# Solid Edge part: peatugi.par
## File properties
Author: Romil
Template: iso part.par
Last saved by: Romil
Revision: 39
Application: Solid Edge
Material: ABS Plastic, medium impact
Face Style: Black
Fill Style: ANSI34(Plastic)
Virtual Style: Black (Shiny)
Coef. of Thermal Exp: 5.8e-05
Thermal Conductivity: 2.0
Specific Heat: 0.0
Modulus of Elasticity: 2275269810.0
Poisson's Ratio: 0.4
Yield Stress: 43436969.1
Ultimate Stress: 0.0
Elongation: 0.0
Density: 1024.000 kg/m^3
Accuracy: 0.990
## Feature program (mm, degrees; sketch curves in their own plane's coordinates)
sketch for "unnamed Protrusion 1" plane through (0, 0, 0) normal (1, 0, 0) x-axis (0, 1, 0)
  arc centre (0, 0) radius 2.35 from (2.181, 0.875) to (2.181, -0.875) cw
  arc centre (0, 0) radius 2.35 from (-0.875, 2.181) to (0.875, 2.181) cw
  arc centre (0, 0) radius 2.35 from (-2.181, -0.875) to (-2.181, 0.875) cw
extrude "unnamed Protrusion 1" add finite 7 along -normal
fillet "Round_8" radius 0.2  Radii2 = 0.2 mm
sketch for "ExtrudedCutout_2" plane through (-7, 0, 0) normal (-1, 0, 0) x-axis (0, 0, 1)
extrude "ExtrudedCutout_2" cut finite 0.1 along -normal
sketch for "unnamed Protrusion 2" plane through (0, 0, 0) normal (0, 0, 1) x-axis (1, 0, 0)
  line (0, -9.7299) -> (6.7203, -2.6937)
  line (0, 9.7299) -> (6.7203, 2.6937)
  line (-10.9663, 11.8304) -> (0, 9.7299)
  line (-11.7, 4.1) -> (0, 4.1)
  line (0, 4.1) -> (0, -4.1)
  line (-11.7, -4.1) -> (0, -4.1)
  line (-10.9663, -11.8304) -> (0, -9.7299)
extrude "unnamed Protrusion 2" add along +normal
sketch for "ExtrudedCutout_5" #1 plane through (0, 0, 0) normal (0, 0, 1) x-axis (1, 0, 0)
  circle centre (-11.7, -8) radius 2.4
sketch for "ExtrudedCutout_5" #2 plane through (0, 0, 0) normal (0, 0, 1) x-axis (1, 0, 0)
  circle centre (-11.7, 8) radius 2.4
sketch for "ExtrudedCutout_5" #3 plane through (0, 0, 0) normal (0, 0, 1) x-axis (1, 0, 0)
  circle centre (3.9, 0) radius 2.4
extrude "ExtrudedCutout_5" cut finite 96.2473 symmetric
sketch for "unnamed Cutout 1" #1 plane through (-3.9, 0, 3.9) normal (0, 0, 1) x-axis (1, 0, 0)
  circle centre (-7.8, 8) radius 3.1
sketch for "unnamed Cutout 1" #2 plane through (-3.9, 0, 3.9) normal (0, 0, 1) x-axis (1, 0, 0)
  arc centre (-7.8, 8) radius 3.9 from (-5.0431, 5.2415) to (-4.5705, 10.1864) ccw
  arc centre (-4.4049, 10.2985) radius 0.2 from (-4.5705, 10.1864) to (-4.3673, 10.495) cw
  line (-4.3673, 10.495) -> (-2.6498, 10.166)
  arc centre (-2.6875, 9.9696) radius 0.2 from (-2.4875, 9.9696) to (-2.6498, 10.166) ccw
  line (-2.4875, 5.1) -> (-2.4875, 9.9696)
  arc centre (-2.6875, 5.1) radius 0.2 from (-2.4875, 5.1) to (-2.6875, 4.9) cw
  line (-4.9017, 4.9) -> (-2.6875, 4.9)
  arc centre (-4.9017, 5.1) radius 0.2 from (-4.9017, 4.9) to (-5.0431, 5.2415) cw
sketch for "unnamed Cutout 1" #3 plane through (-3.9, 0, 3.9) normal (0, 0, 1) x-axis (1, 0, 0)
  line (-1.7648, 5.1) -> (-1.7648, 9.7545)
  arc centre (-1.5648, 9.7545) radius 0.2 from (-1.7648, 9.7545) to (-1.5272, 9.951) cw
  line (-1.5272, 9.951) -> (-0.0678, 9.6715)
  arc centre (-0.1054, 9.475) radius 0.2 from (0.0946, 9.475) to (-0.0678, 9.6715) ccw
  line (0.0946, 5.1) -> (0.0946, 9.475)
  arc centre (-0.1054, 5.1) radius 0.2 from (0.0946, 5.1) to (-0.1054, 4.9) cw
  line (-1.5648, 4.9) -> (-0.1054, 4.9)
  arc centre (-1.5648, 5.1) radius 0.2 from (-1.7648, 5.1) to (-1.5648, 4.9) ccw
sketch for "unnamed Cutout 1" #4 plane through (-3.9, 0, 3.9) normal (0, 0, 1) x-axis (1, 0, 0)
  line (0.9365, 5.1) -> (0.9365, 9.2371)
  arc centre (1.1365, 9.2371) radius 0.2 from (1.1742, 9.4336) to (0.9365, 9.2371) ccw
  line (1.1742, 9.4336) -> (3.4378, 9)
  arc centre (3.4002, 8.8036) radius 0.2 from (3.4378, 9) to (3.5448, 8.9417) cw
  line (3.5448, 8.9417) -> (3.8446, 8.6278)
  arc centre (3.7, 8.4897) radius 0.2 from (3.9, 8.4897) to (3.8446, 8.6278) ccw
  line (3.9, 5.1) -> (3.9, 8.4897)
  arc centre (3.7, 5.1) radius 0.2 from (3.7, 4.9) to (3.9, 5.1) ccw
  line (1.1365, 4.9) -> (3.7, 4.9)
  arc centre (1.1365, 5.1) radius 0.2 from (1.1365, 4.9) to (0.9365, 5.1) cw
sketch for "unnamed Cutout 1" #5 plane through (-3.9, 0, 3.9) normal (0, 0, 1) x-axis (1, 0, 0)
  line (4.7, 4.018) -> (4.7, 7.2332)
  arc centre (4.9, 7.2332) radius 0.2 from (4.7, 7.2332) to (5.0446, 7.3714) cw
  line (5.0446, 7.3714) -> (7.405, 4.9)
  line (7.405, 4.9) -> (8.0382, 4.2371)
  arc centre (7.8936, 4.0989) radius 0.2 from (8.0382, 4.2371) to (7.889, 3.899) cw
  arc centre (7.8, 0) radius 3.9 from (7.889, 3.899) to (5.0415, 2.7569) ccw
  arc centre (4.9, 2.8983) radius 0.2 from (5.0415, 2.7569) to (4.7, 2.8983) cw
  line (4.7, 4.018) -> (4.7, 2.8983)
sketch for "unnamed Cutout 1" #6 plane through (-3.9, 0, 3.9) normal (0, 0, 1) x-axis (1, 0, 0)
  arc centre (7.8, 0) radius 3.9 from (7.889, -3.899) to (5.0415, -2.7569) cw
  arc centre (4.9, -2.8983) radius 0.2 from (5.0415, -2.7569) to (4.7, -2.8983) ccw
  line (4.7, -4.018) -> (4.7, -2.8983)
  line (4.7, -4.018) -> (4.7, -7.2332)
  arc centre (4.9, -7.2332) radius 0.2 from (4.7, -7.2332) to (5.0446, -7.3714) ccw
  line (5.0446, -7.3714) -> (7.405, -4.9)
  line (7.405, -4.9) -> (8.0382, -4.2371)
  arc centre (7.8936, -4.0989) radius 0.2 from (8.0382, -4.2371) to (7.889, -3.899) ccw
sketch for "unnamed Cutout 1" #7 plane through (-3.9, 0, 3.9) normal (0, 0, 1) x-axis (1, 0, 0)
  circle centre (7.8, 0) radius 3.1
sketch for "unnamed Cutout 1" #8 plane through (-3.9, 0, 3.9) normal (0, 0, 1) x-axis (1, 0, 0)
  line (1.1365, -4.9) -> (3.7, -4.9)
  arc centre (3.7, -5.1) radius 0.2 from (3.7, -4.9) to (3.9, -5.1) cw
  line (3.9, -5.1) -> (3.9, -8.4897)
  arc centre (3.7, -8.4897) radius 0.2 from (3.9, -8.4897) to (3.8446, -8.6278) cw
  line (3.5448, -8.9417) -> (3.8446, -8.6278)
  arc centre (3.4002, -8.8036) radius 0.2 from (3.4378, -9) to (3.5448, -8.9417) ccw
  line (1.1742, -9.4336) -> (3.4378, -9)
  arc centre (1.1365, -9.2371) radius 0.2 from (1.1742, -9.4336) to (0.9365, -9.2371) cw
  line (0.9365, -5.1) -> (0.9365, -9.2371)
  arc centre (1.1365, -5.1) radius 0.2 from (1.1365, -4.9) to (0.9365, -5.1) ccw
sketch for "unnamed Cutout 1" #9 plane through (-3.9, 0, 3.9) normal (0, 0, 1) x-axis (1, 0, 0)
  line (0.0946, -5.1) -> (0.0946, -9.475)
  arc centre (-0.1054, -9.475) radius 0.2 from (0.0946, -9.475) to (-0.0678, -9.6715) cw
  line (-1.5272, -9.951) -> (-0.0678, -9.6715)
  arc centre (-1.5648, -9.7545) radius 0.2 from (-1.7648, -9.7545) to (-1.5272, -9.951) ccw
  line (-1.7648, -5.1) -> (-1.7648, -9.7545)
  arc centre (-1.5648, -5.1) radius 0.2 from (-1.7648, -5.1) to (-1.5648, -4.9) cw
  line (-1.5648, -4.9) -> (-0.1054, -4.9)
  arc centre (-0.1054, -5.1) radius 0.2 from (0.0946, -5.1) to (-0.1054, -4.9) ccw
sketch for "unnamed Cutout 1" #10 plane through (-3.9, 0, 3.9) normal (0, 0, 1) x-axis (1, 0, 0)
  line (-2.4875, -5.1) -> (-2.4875, -9.9696)
  arc centre (-2.6875, -9.9696) radius 0.2 from (-2.4875, -9.9696) to (-2.6498, -10.166) cw
  line (-4.3673, -10.495) -> (-2.6498, -10.166)
  arc centre (-4.4049, -10.2985) radius 0.2 from (-4.5705, -10.1864) to (-4.3673, -10.495) ccw
  arc centre (-7.8, -8) radius 3.9 from (-5.0431, -5.2415) to (-4.5705, -10.1864) cw
  arc centre (-4.9017, -5.1) radius 0.2 from (-4.9017, -4.9) to (-5.0431, -5.2415) ccw
  line (-4.9017, -4.9) -> (-2.6875, -4.9)
  arc centre (-2.6875, -5.1) radius 0.2 from (-2.4875, -5.1) to (-2.6875, -4.9) ccw
sketch for "unnamed Cutout 1" #11 plane through (-3.9, 0, 3.9) normal (0, 0, 1) x-axis (1, 0, 0)
  circle centre (-7.8, -8) radius 3.1
extrude "unnamed Cutout 1" cut finite 0.9 along -normal
sketch for "unnamed Cutout 2" #1 plane through (-3.8864, -7.6594, -3.9) normal (0, 0, -1) x-axis (0, 1, 0)
  line (2.7594, 1.123) -> (2.7594, 3.6864)
  arc centre (2.5594, 3.6864) radius 0.2 from (2.7594, 3.6864) to (2.5594, 3.8864) ccw
  line (2.5594, 3.8864) -> (-0.8303, 3.8864)
  arc centre (-0.8303, 3.6864) radius 0.2 from (-0.8303, 3.8864) to (-0.9684, 3.8311) ccw
  line (-1.2824, 3.5313) -> (-0.9684, 3.8311)
  arc centre (-1.1442, 3.3866) radius 0.2 from (-1.3406, 3.4243) to (-1.2824, 3.5313) cw
  line (-2.5067, -2.6634) -> (-1.3406, 3.4243)
  line (-2.8356, -4.3808) -> (-2.5067, -2.6634)
  arc centre (-2.6392, -4.4184) radius 0.2 from (-2.5271, -4.5841) to (-2.8356, -4.3808) cw
  arc centre (-0.3406, -7.8136) radius 3.9 from (2.4179, -5.0567) to (-2.5271, -4.5841) ccw
  arc centre (2.5594, -4.9153) radius 0.2 from (2.7594, -4.9153) to (2.4179, -5.0567) cw
  line (2.7594, -4.9153) -> (2.7594, -2.701)
  line (2.7594, -2.701) -> (2.7594, 1.123)
sketch for "unnamed Cutout 2" #2 plane through (-3.8864, -7.6594, -3.9) normal (0, 0, -1) x-axis (0, 1, 0)
  line (12.5594, 1.123) -> (12.5594, -2.701)
  line (12.5594, -4.9153) -> (12.5594, -2.701)
  arc centre (12.7594, -4.9153) radius 0.2 from (12.5594, -4.9153) to (12.9008, -5.0567) ccw
  arc centre (15.6594, -7.8136) radius 3.9 from (12.9008, -5.0567) to (17.8458, -4.5841) cw
  arc centre (17.9579, -4.4184) radius 0.2 from (17.8458, -4.5841) to (18.1543, -4.3808) ccw
  line (18.1543, -4.3808) -> (17.8254, -2.6634)
  line (17.8254, -2.6634) -> (17.0929, 1.1606)
  line (17.0929, 1.1606) -> (16.6594, 3.4243)
  arc centre (16.4629, 3.3866) radius 0.2 from (16.6594, 3.4243) to (16.6011, 3.5313) ccw
  line (16.6011, 3.5313) -> (16.2872, 3.8311)
  arc centre (16.149, 3.6864) radius 0.2 from (16.149, 3.8864) to (16.2872, 3.8311) cw
  line (12.7594, 3.8864) -> (16.149, 3.8864)
  arc centre (12.7594, 3.6864) radius 0.2 from (12.5594, 3.6864) to (12.7594, 3.8864) cw
  line (12.5594, 1.123) -> (12.5594, 3.6864)
sketch for "unnamed Cutout 2" #3 plane through (-3.8864, -7.6594, -3.9) normal (0, 0, -1) x-axis (0, 1, 0)
  line (3.6413, 4.6864) -> (4.7611, 4.6864)
  arc centre (4.7611, 4.8864) radius 0.2 from (4.9025, 5.0279) to (4.7611, 4.6864) cw
  arc centre (7.6594, 7.7864) radius 3.9 from (3.7604, 7.8755) to (4.9025, 5.0279) ccw
  arc centre (3.5604, 7.88) radius 0.2 from (3.4223, 8.0247) to (3.7604, 7.8755) cw
  line (2.7594, 7.3915) -> (3.4223, 8.0247)
  line (0.288, 5.0311) -> (2.7594, 7.3915)
  arc centre (0.4261, 4.8864) radius 0.2 from (0.4261, 4.6864) to (0.288, 5.0311) cw
  line (3.6413, 4.6864) -> (0.4261, 4.6864)
sketch for "unnamed Cutout 2" #4 plane through (-3.8864, -7.6594, -3.9) normal (0, 0, -1) x-axis (0, 1, 0)
  line (11.6774, 4.6864) -> (10.5576, 4.6864)
  arc centre (10.5576, 4.8864) radius 0.2 from (10.4163, 5.0279) to (10.5576, 4.6864) ccw
  arc centre (7.6594, 7.7864) radius 3.9 from (11.5583, 7.8755) to (10.4163, 5.0279) cw
  arc centre (11.7583, 7.88) radius 0.2 from (11.8964, 8.0247) to (11.5583, 7.8755) ccw
  line (12.5594, 7.3915) -> (11.8964, 8.0247)
  line (15.0307, 5.0311) -> (12.5594, 7.3915)
  arc centre (14.8926, 4.8864) radius 0.2 from (14.8926, 4.6864) to (15.0307, 5.0311) ccw
  line (11.6774, 4.6864) -> (14.8926, 4.6864)
extrude "unnamed Cutout 2" cut finite 5.9 along -normal
sketch for "ExtrudedCutout_8" #1 plane through (-3.8864, -7.6594, -3.9) normal (0, 0, -1) x-axis (0, 1, 0)
  circle centre (-0.3406, -7.8136) radius 3.1
sketch for "ExtrudedCutout_8" #2 plane through (-3.8864, -7.6594, -3.9) normal (0, 0, -1) x-axis (0, 1, 0)
  circle centre (15.6594, -7.8136) radius 3.1
sketch for "ExtrudedCutout_8" #3 plane through (-3.8864, -7.6594, -3.9) normal (0, 0, -1) x-axis (0, 1, 0)
  circle centre (7.6594, 7.7864) radius 3.1
extrude "ExtrudedCutout_8" cut finite 4.5 along -normal
draft "Draft"  Angles1 = 62 deg
chamfer "Chamfer_2" setback 0.1
rib "Rib_1"  Plane_Distance = 7 mm; Thickness = 2.7 mm
mirror "unnamed Mirror 1" of "Rib_1" about plane through (0, 0, 0) normal (0, -1, 0)
rib "unnamed Rib 1"
Other named dimensions: "ExtrudedSurface_2": FiniteDepth = 161.4252 mm
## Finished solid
Body 1: sheet body, 1 face, 4 edges, 4 vertices.
  Faces by surface: plane 1
  Edges by curve: line 4
Body 2: sheet body, 5 faces, 16 edges, 12 vertices.
  Faces by surface: plane 5
  Edges by curve: line 16
Body 3: solid body, 194 faces, 484 edges, 300 vertices.
  Faces by surface: plane 93, cylinder 85, spline 8, torus 8
  Edges by curve: line 278, circle 150, curve on surface 28, intersection 16, ellipse 12
Bounding box of the edges (mm; curved faces can reach further): 28.775 x 357.614 x 7.800, from (-18.514, -178.8071, -3.9) to (10.2611, 178.8071, 3.9).
Cylindrical faces by radius (mm): R0.1 x4, R0.2 x57, R2.35 x4, R2.4 x3, R3.1 x6, R3.9 x11
Toroidal faces (ring radius, tube radius in mm): R0.3 r0.2 x4, R1.8 r0.55 x4
Planar faces by outward normal: +x 8, +y 9, +z 14, -x 11, -y 9, -z 13, oblique 29
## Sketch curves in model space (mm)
circle centre (3.9, 0, -3.9) radius 3.1
circle centre (-11.7, 8, -3.9) radius 3.1
circle centre (-11.7, -8, -3.9) radius 3.1
arc centre (1, -2.8983, -3.9) radius 0.2 from (1.1415, -2.7569, -3.9) through (0.9235, -2.7135, -3.9) to (0.8, -2.8983, -3.9)
line (0.8, -4.018, -3.9) -> (0.8, -2.8983, -3.9)
line (0.8, -4.018, -3.9) -> (0.8, -7.2332, -3.9)
arc centre (1, -7.2332, -3.9) radius 0.2 from (0.8, -7.2332, -3.9) through (0.9256, -7.4189, -3.9) to (1.1446, -7.3714, -3.9)
line (1.1446, -7.3714, -3.9) -> (3.505, -4.9, -3.9)
line (3.505, -4.9, -3.9) -> (4.1382, -4.2371, -3.9)
arc centre (3.9936, -4.0989, -3.9) radius 0.2 from (4.1382, -4.2371, -3.9) through (4.1766, -4.0182, -3.9) to (3.989, -3.899, -3.9)
arc centre (3.9, 0, -3.9) radius 3.9 from (3.989, -3.899, -3.9) through (2.4482, -3.6197, -3.9) to (1.1415, -2.7569, -3.9)
arc centre (1, 2.8983, -3.9) radius 0.2 from (1.1415, 2.7569, -3.9) through (0.9235, 2.7135, -3.9) to (0.8, 2.8983, -3.9)
line (0.8, 4.018, -3.9) -> (0.8, 2.8983, -3.9)
line (0.8, 4.018, -3.9) -> (0.8, 7.2332, -3.9)
arc centre (1, 7.2332, -3.9) radius 0.2 from (0.8, 7.2332, -3.9) through (0.9256, 7.4189, -3.9) to (1.1446, 7.3714, -3.9)
line (1.1446, 7.3714, -3.9) -> (3.505, 4.9, -3.9)
line (3.505, 4.9, -3.9) -> (4.1382, 4.2371, -3.9)
arc centre (3.9936, 4.0989, -3.9) radius 0.2 from (4.1382, 4.2371, -3.9) through (4.1766, 4.0182, -3.9) to (3.989, 3.899, -3.9)
arc centre (3.9, 0, -3.9) radius 3.9 from (3.989, 3.899, -3.9) through (2.4482, 3.6197, -3.9) to (1.1415, 2.7569, -3.9)
arc centre (-0.2, 5.1, -3.9) radius 0.2 from (-0.2, 4.9, -3.9) through (-0.0545, 4.9628, -3.9) to (0, 5.1, -3.9)
line (0, 5.1, -3.9) -> (0, 8.4897, -3.9)
arc centre (-0.2, 8.4897, -3.9) radius 0.2 from (0, 8.4897, -3.9) through (-0.0144, 8.5641, -3.9) to (-0.0554, 8.6278, -3.9)
line (-0.3552, 8.9417, -3.9) -> (-0.0554, 8.6278, -3.9)
arc centre (-0.4998, 8.8036, -3.9) radius 0.2 from (-0.4622, 9, -3.9) through (-0.4041, 8.9792, -3.9) to (-0.3552, 8.9417, -3.9)
line (-2.7258, 9.4336, -3.9) -> (-0.4622, 9, -3.9)
line (-6.5498, 10.166, -3.9) -> (-2.7258, 9.4336, -3.9)
line (-8.2673, 10.495, -3.9) -> (-6.5498, 10.166, -3.9)
arc centre (-8.3049, 10.2985, -3.9) radius 0.2 from (-8.4705, 10.1864, -3.9) through (-8.4719, 10.4085, -3.9) to (-8.2673, 10.495, -3.9)
arc centre (-11.7, 8, -3.9) radius 3.9 from (-8.9431, 5.2415, -3.9) through (-7.8177, 7.629, -3.9) to (-8.4705, 10.1864, -3.9)
arc centre (-8.8017, 5.1, -3.9) radius 0.2 from (-8.8017, 4.9, -3.9) through (-8.9865, 5.0235, -3.9) to (-8.9431, 5.2415, -3.9)
line (-8.8017, 4.9, -3.9) -> (-6.5875, 4.9, -3.9)
line (-2.7635, 4.9, -3.9) -> (-6.5875, 4.9, -3.9)
line (-2.7635, 4.9, -3.9) -> (-0.2, 4.9, -3.9)
line (-6.5875, -4.9, -3.9) -> (-2.7635, -4.9, -3.9)
line (-2.7635, -4.9, -3.9) -> (-0.2, -4.9, -3.9)
arc centre (-0.2, -5.1, -3.9) radius 0.2 from (-0.2, -4.9, -3.9) through (-0.0545, -4.9628, -3.9) to (0, -5.1, -3.9)
line (0, -5.1, -3.9) -> (0, -8.4897, -3.9)
arc centre (-0.2, -8.4897, -3.9) radius 0.2 from (0, -8.4897, -3.9) through (-0.0144, -8.5641, -3.9) to (-0.0554, -8.6278, -3.9)
line (-0.3552, -8.9417, -3.9) -> (-0.0554, -8.6278, -3.9)
arc centre (-0.4998, -8.8036, -3.9) radius 0.2 from (-0.4622, -9, -3.9) through (-0.4041, -8.9792, -3.9) to (-0.3552, -8.9417, -3.9)
line (-6.5498, -10.166, -3.9) -> (-0.4622, -9, -3.9)
line (-8.2673, -10.495, -3.9) -> (-6.5498, -10.166, -3.9)
arc centre (-8.3049, -10.2985, -3.9) radius 0.2 from (-8.4705, -10.1864, -3.9) through (-8.4719, -10.4085, -3.9) to (-8.2673, -10.495, -3.9)
arc centre (-11.7, -8, -3.9) radius 3.9 from (-8.9431, -5.2415, -3.9) through (-7.8177, -7.629, -3.9) to (-8.4705, -10.1864, -3.9)
arc centre (-8.8017, -5.1, -3.9) radius 0.2 from (-8.8017, -4.9, -3.9) through (-8.9865, -5.0235, -3.9) to (-8.9431, -5.2415, -3.9)
line (-8.8017, -4.9, -3.9) -> (-6.5875, -4.9, -3.9)
circle centre (-11.7, -8, 3.9) radius 3.1
circle centre (3.9, 0, 3.9) radius 3.1
circle centre (-11.7, 8, 3.9) radius 3.1
line (-8.2673, 10.495, 3.9) -> (-6.5498, 10.166, 3.9)
arc centre (-6.5875, 9.9696, 3.9) radius 0.2 from (-6.3875, 9.9696, 3.9) through (-6.4333, 10.097, 3.9) to (-6.5498, 10.166, 3.9)
line (-6.3875, 5.1, 3.9) -> (-6.3875, 9.9696, 3.9)
arc centre (-6.5875, 5.1, 3.9) radius 0.2 from (-6.3875, 5.1, 3.9) through (-6.4502, 4.9545, 3.9) to (-6.5875, 4.9, 3.9)
line (-8.8017, 4.9, 3.9) -> (-6.5875, 4.9, 3.9)
arc centre (-8.8017, 5.1, 3.9) radius 0.2 from (-8.8017, 4.9, 3.9) through (-8.9865, 5.0235, 3.9) to (-8.9431, 5.2415, 3.9)
arc centre (-11.7, 8, 3.9) radius 3.9 from (-8.9431, 5.2415, 3.9) through (-7.8177, 7.629, 3.9) to (-8.4705, 10.1864, 3.9)
arc centre (-8.3049, 10.2985, 3.9) radius 0.2 from (-8.4705, 10.1864, 3.9) through (-8.4719, 10.4085, 3.9) to (-8.2673, 10.495, 3.9)
line (-5.4272, 9.951, 3.9) -> (-3.9678, 9.6715, 3.9)
arc centre (-4.0054, 9.475, 3.9) radius 0.2 from (-3.8054, 9.475, 3.9) through (-3.8513, 9.6025, 3.9) to (-3.9678, 9.6715, 3.9)
line (-3.8054, 5.1, 3.9) -> (-3.8054, 9.475, 3.9)
arc centre (-4.0054, 5.1, 3.9) radius 0.2 from (-3.8054, 5.1, 3.9) through (-3.8682, 4.9545, 3.9) to (-4.0054, 4.9, 3.9)
line (-5.4648, 4.9, 3.9) -> (-4.0054, 4.9, 3.9)
arc centre (-5.4648, 5.1, 3.9) radius 0.2 from (-5.6648, 5.1, 3.9) through (-5.602, 4.9545, 3.9) to (-5.4648, 4.9, 3.9)
line (-5.6648, 5.1, 3.9) -> (-5.6648, 9.7545, 3.9)
arc centre (-5.4648, 9.7545, 3.9) radius 0.2 from (-5.6648, 9.7545, 3.9) through (-5.5922, 9.9087, 3.9) to (-5.4272, 9.951, 3.9)
arc centre (-0.4998, 8.8036, 3.9) radius 0.2 from (-0.4622, 9, 3.9) through (-0.4041, 8.9792, 3.9) to (-0.3552, 8.9417, 3.9)
line (-0.3552, 8.9417, 3.9) -> (-0.0554, 8.6278, 3.9)
arc centre (-0.2, 8.4897, 3.9) radius 0.2 from (0, 8.4897, 3.9) through (-0.0144, 8.5641, 3.9) to (-0.0554, 8.6278, 3.9)
line (0, 5.1, 3.9) -> (0, 8.4897, 3.9)
arc centre (-0.2, 5.1, 3.9) radius 0.2 from (-0.2, 4.9, 3.9) through (-0.0545, 4.9628, 3.9) to (0, 5.1, 3.9)
line (-2.7635, 4.9, 3.9) -> (-0.2, 4.9, 3.9)
arc centre (-2.7635, 5.1, 3.9) radius 0.2 from (-2.7635, 4.9, 3.9) through (-2.9089, 4.9628, 3.9) to (-2.9635, 5.1, 3.9)
line (-2.9635, 5.1, 3.9) -> (-2.9635, 9.2371, 3.9)
arc centre (-2.7635, 9.2371, 3.9) radius 0.2 from (-2.7258, 9.4336, 3.9) through (-2.8909, 9.3913, 3.9) to (-2.9635, 9.2371, 3.9)
line (-2.7258, 9.4336, 3.9) -> (-0.4622, 9, 3.9)
arc centre (1, 7.2332, 3.9) radius 0.2 from (0.8, 7.2332, 3.9) through (0.9256, 7.4189, 3.9) to (1.1446, 7.3714, 3.9)
line (1.1446, 7.3714, 3.9) -> (3.505, 4.9, 3.9)
line (3.505, 4.9, 3.9) -> (4.1382, 4.2371, 3.9)
arc centre (3.9936, 4.0989, 3.9) radius 0.2 from (4.1382, 4.2371, 3.9) through (4.1766, 4.0182, 3.9) to (3.989, 3.899, 3.9)
arc centre (3.9, 0, 3.9) radius 3.9 from (3.989, 3.899, 3.9) through (2.4482, 3.6197, 3.9) to (1.1415, 2.7569, 3.9)
arc centre (1, 2.8983, 3.9) radius 0.2 from (1.1415, 2.7569, 3.9) through (0.9235, 2.7135, 3.9) to (0.8, 2.8983, 3.9)
line (0.8, 4.018, 3.9) -> (0.8, 2.8983, 3.9)
line (0.8, 4.018, 3.9) -> (0.8, 7.2332, 3.9)
arc centre (1, -2.8983, 3.9) radius 0.2 from (1.1415, -2.7569, 3.9) through (0.9235, -2.7135, 3.9) to (0.8, -2.8983, 3.9)
line (0.8, -4.018, 3.9) -> (0.8, -2.8983, 3.9)
line (0.8, -4.018, 3.9) -> (0.8, -7.2332, 3.9)
arc centre (1, -7.2332, 3.9) radius 0.2 from (0.8, -7.2332, 3.9) through (0.9256, -7.4189, 3.9) to (1.1446, -7.3714, 3.9)
line (1.1446, -7.3714, 3.9) -> (3.505, -4.9, 3.9)
line (3.505, -4.9, 3.9) -> (4.1382, -4.2371, 3.9)
arc centre (3.9936, -4.0989, 3.9) radius 0.2 from (4.1382, -4.2371, 3.9) through (4.1766, -4.0182, 3.9) to (3.989, -3.899, 3.9)
arc centre (3.9, 0, 3.9) radius 3.9 from (3.989, -3.899, 3.9) through (2.4482, -3.6197, 3.9) to (1.1415, -2.7569, 3.9)
arc centre (-0.2, -5.1, 3.9) radius 0.2 from (-0.2, -4.9, 3.9) through (-0.0545, -4.9628, 3.9) to (0, -5.1, 3.9)
line (0, -5.1, 3.9) -> (0, -8.4897, 3.9)
arc centre (-0.2, -8.4897, 3.9) radius 0.2 from (0, -8.4897, 3.9) through (-0.0144, -8.5641, 3.9) to (-0.0554, -8.6278, 3.9)
line (-0.3552, -8.9417, 3.9) -> (-0.0554, -8.6278, 3.9)
arc centre (-0.4998, -8.8036, 3.9) radius 0.2 from (-0.4622, -9, 3.9) through (-0.4041, -8.9792, 3.9) to (-0.3552, -8.9417, 3.9)
line (-2.7258, -9.4336, 3.9) -> (-0.4622, -9, 3.9)
arc centre (-2.7635, -9.2371, 3.9) radius 0.2 from (-2.7258, -9.4336, 3.9) through (-2.8909, -9.3913, 3.9) to (-2.9635, -9.2371, 3.9)
line (-2.9635, -5.1, 3.9) -> (-2.9635, -9.2371, 3.9)
arc centre (-2.7635, -5.1, 3.9) radius 0.2 from (-2.7635, -4.9, 3.9) through (-2.9089, -4.9628, 3.9) to (-2.9635, -5.1, 3.9)
line (-2.7635, -4.9, 3.9) -> (-0.2, -4.9, 3.9)
arc centre (-4.0054, -5.1, 3.9) radius 0.2 from (-3.8054, -5.1, 3.9) through (-3.8682, -4.9545, 3.9) to (-4.0054, -4.9, 3.9)
line (-3.8054, -5.1, 3.9) -> (-3.8054, -9.475, 3.9)
arc centre (-4.0054, -9.475, 3.9) radius 0.2 from (-3.8054, -9.475, 3.9) through (-3.8513, -9.6025, 3.9) to (-3.9678, -9.6715, 3.9)
line (-5.4272, -9.951, 3.9) -> (-3.9678, -9.6715, 3.9)
arc centre (-5.4648, -9.7545, 3.9) radius 0.2 from (-5.6648, -9.7545, 3.9) through (-5.5922, -9.9087, 3.9) to (-5.4272, -9.951, 3.9)
line (-5.6648, -5.1, 3.9) -> (-5.6648, -9.7545, 3.9)
arc centre (-5.4648, -5.1, 3.9) radius 0.2 from (-5.6648, -5.1, 3.9) through (-5.602, -4.9545, 3.9) to (-5.4648, -4.9, 3.9)
line (-5.4648, -4.9, 3.9) -> (-4.0054, -4.9, 3.9)
line (-8.8017, -4.9, 3.9) -> (-6.5875, -4.9, 3.9)
arc centre (-8.8017, -5.1, 3.9) radius 0.2 from (-8.8017, -4.9, 3.9) through (-8.9865, -5.0235, 3.9) to (-8.9431, -5.2415, 3.9)
arc centre (-11.7, -8, 3.9) radius 3.9 from (-8.9431, -5.2415, 3.9) through (-7.8177, -7.629, 3.9) to (-8.4705, -10.1864, 3.9)
arc centre (-8.3049, -10.2985, 3.9) radius 0.2 from (-8.4705, -10.1864, 3.9) through (-8.4719, -10.4085, 3.9) to (-8.2673, -10.495, 3.9)
line (-8.2673, -10.495, 3.9) -> (-6.5498, -10.166, 3.9)
arc centre (-6.5875, -9.9696, 3.9) radius 0.2 from (-6.3875, -9.9696, 3.9) through (-6.4333, -10.097, 3.9) to (-6.5498, -10.166, 3.9)
line (-6.3875, -5.1, 3.9) -> (-6.3875, -9.9696, 3.9)
arc centre (-6.5875, -5.1, 3.9) radius 0.2 from (-6.3875, -5.1, 3.9) through (-6.4502, -4.9545, 3.9) to (-6.5875, -4.9, 3.9)
line (10.2611, 0, 3.9) -> (-18.3829, 0, 3.9)
line (-15.6, 0, 0) -> (-18.514, 0, 0)
line (-15.6, 0, 0) -> (-7.7729, 0, -3.9)
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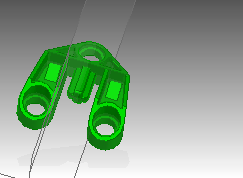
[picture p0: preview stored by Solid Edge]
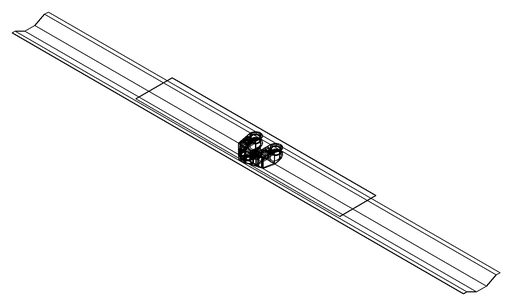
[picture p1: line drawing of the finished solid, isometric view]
